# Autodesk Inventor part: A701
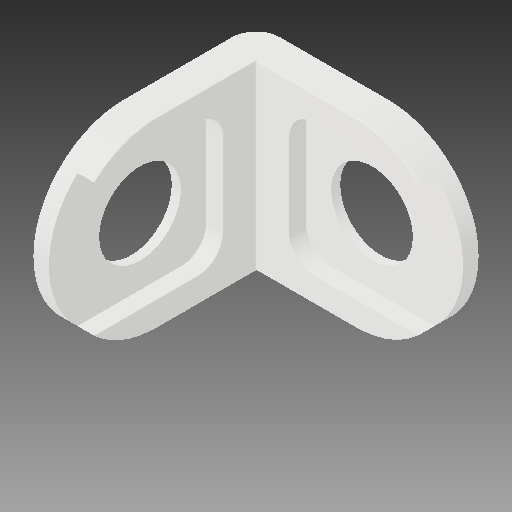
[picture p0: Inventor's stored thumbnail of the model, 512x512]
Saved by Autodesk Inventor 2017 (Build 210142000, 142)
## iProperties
Part Number: A701
Material: Générique
Document SubType Name: Modeling
Designer: ficho
Density: 1 g/cm^3
Appearance: Par défaut
Author: ficho
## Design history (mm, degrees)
feature "Solid1"
node "Solide1"
